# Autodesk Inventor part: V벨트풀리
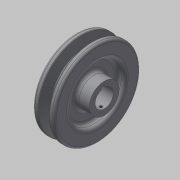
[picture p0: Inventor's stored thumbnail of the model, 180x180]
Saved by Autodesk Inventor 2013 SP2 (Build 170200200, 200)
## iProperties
Created: 2015-11
Part Number: V벨트풀리
Material: 강철, 탄소
Document SubType Name: Modeling
Designer: mduedu
Density: 1 g/cm^3
Author: mduedu
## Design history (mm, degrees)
sketch "스케치1"
  geometry: L1 (-9.5, 0)-(9.5, 0); L2 (0, 0)-(0, 37.7); L3 (-4.825, 37.7)-(-9.5, 37.7); L4 (-9.5, 37.7)-(-9.5, 0); L5 (0, 28.7)-(-2.074, 28.7); L6 (-2.074, 28.7)-(-4.825, 37.7); L7 (4.825, 37.7)-(9.5, 37.7); L8 (9.5, 37.7)-(9.5, 0); L9 (0, 28.7)-(2.074, 28.7); L10 (2.074, 28.7)-(4.825, 37.7); L11 (-9.5, 35)-(9.5, 35); 3 further points
  constraints: 22 end point, 7 point on line, 4 perpendicular, 3 symmetric about line, 1 coincident, 1 horizontal, 1 horizontal alignment, 1 midpoint, 1 vertical
  dimensions: "d0" = 19 distance of L1.start L1.end; "d2" = 75.4 diameter of L2.end L1 (derived); "d3" = 34 deg angle of L10 L6; "d4" = 6.3 distance between parallel lines of L11 L9; "d5" = 2.7 distance between parallel lines of L7 L11; "d6" = 8 distance of point (4, 35) point (-4, 35); "d7" = 70 diameter of L11 L1
revolve "회전1" sketch "스케치1" stored, may be unused: angle "d8" = 90 deg
sketch "스케치2"
  geometry: C1 r 24 at (0, 0); C2 r 13 at (0, 0); 1 further point
  constraints: 2 centre point, 2 coincident
  dimensions: "d9" = 48 diameter of C1; "d10" = 26 diameter of C2
extrude "돌출1" cut sketch "스케치2" distance "d11" = 6; taper "d12" = 0 deg
extrude "돌출3" join sketch "스케치2" distance "d37" = 6; taper "d38" = 0 deg
fillet "모깎기1" dims "d13" = 3
fillet "모깎기2" dims "d14" = 3
fillet "모깎기3" dims "d15" = 1, "d16" = 0.5, "d17" = 2
hole "구멍1" diameter "d20" = 16; stored, may be unused: countersink angle "d24" = 90 deg, drill point angle "d26" = 118 deg; dims "d21" = 6, "d22" = 4, "d23" = 2, "d25" = 8, "d53" = 10, "d54" = 10
sketch "스케치3"
  geometry: L1 (-2.5, 0)-(2.5, 0); L2 (2.5, 0)-(2.5, 10.3); L3 (2.5, 10.3)-(-2.5, 10.3); L4 (-2.5, 10.3)-(-2.5, 0); 2 further points
  constraints: 8 end point, 2 parallel, 1 coincident, 1 horizontal, 1 midpoint, 1 perpendicular
  dimensions: "d27" = 5 distance of L2.end L3.end; "d29" = 10.3 distance of L3.end L1.start
extrude "돌출2" cut sketch "스케치3" stored distance "d30" = 6; taper "d31" = 0 deg
chamfer "모따기1" distance "d32" = 1; stored, may be unused: second distance "d33" = 2, angle "d34" = 45 deg
node "작업 평면1"
sketch "스케치4"
  geometry: L1 (19, -27)-(19, 27) reference; 2 further points
  constraints: 1 horizontal alignment
  dimensions: "d52" = 22 distance from line of L1 point (-3, 0)
hole "구멍2" sketch "스케치4" at (-3, 0) diameter "d42" = 2.459; stored, may be unused: countersink angle "d46" = 90 deg, drill point angle "d48" = 118 deg; dims "d43" = 6, "d44" = 4, "d45" = 2, "d47" = 8
node "솔리드1"
mirror "대칭1"
